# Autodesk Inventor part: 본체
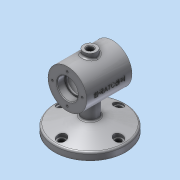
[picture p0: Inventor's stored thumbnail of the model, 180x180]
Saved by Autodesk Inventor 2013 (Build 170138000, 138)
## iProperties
Created: 2018-12
Part Number: 본체
Material: 알루미늄 6061
Document SubType Name: Modeling
Designer: Administrator
Density: 2.71 g/cm^3
Mass: 687.618 g
Surface Area: 555.466 cm^2
Volume: 253.733 cm^3
Author: Administrator
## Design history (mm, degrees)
sketch "스케치1"
  geometry: C1 r 30 at (0, 0); 1 further point
  constraints: 1 centre point, 1 coincident
  dimensions: "d0" = 60 diameter of C1
extrude "돌출1" new body sketch "스케치1" distance "d1" = 35; taper "d2" = 0 deg
sketch "스케치2"
  geometry: C1 r 30 at (0, 0) reference; C2 r 16 at (0, 0)
  constraints: 1 centre point, 1 coincident
  dimensions: "d4" = 32 diameter of C2
extrude "돌출2" cut sketch "스케치2" distance "d5" = 12; taper "d6" = 0 deg
sketch "스케치3"
  geometry: C1 r 16 at (0, 0) reference; C2 r 14 at (0, 0)
  constraints: 1 centre point, 1 coincident
  dimensions: "d7" = 28 diameter of C2
extrude "돌출3" cut sketch "스케치3" distance "d8" = 3; taper "d9" = 0 deg
sketch "스케치4"
  geometry: C1 r 14 at (0, 0) reference; C2 r 25 at (0, 0)
  constraints: 1 centre point, 1 coincident
  dimensions: "d10" = 50 diameter of C2
extrude "돌출4" cut sketch "스케치4" stored distance "d11" = 3; taper "d12" = 0 deg
fillet "모깎기1" dims "d13" = 3
chamfer "모따기1" distance "d14" = 1; stored, may be unused: second distance "d15" = 2, angle "d16" = 45 deg
fillet "모깎기2" dims "d17" = 0.3
sketch "스케치5" dims "d18" = 46
  geometry: C1 r 30 at (0, 0) reference; C2 r 17 at (0, 0) reference; 2 further points
  constraints: 2 vertical alignment, 1 coincident, 2 other
hole "구멍1" sketch "스케치5" at (0, 23) diameter "d19" = 3.242; stored, may be unused: countersink angle "d23" = 90 deg, drill point angle "d25" = 118 deg; dims "d20" = 8, "d21" = 4, "d22" = 2, "d24" = 10
node "작업 평면1"
sketch "스케치6"
  geometry: C1 r 55 at (0, 0); 1 further point
  constraints: 1 centre point, 1 coincident
  dimensions: "d30" = 110 diameter of C1
extrude "돌출5" join sketch "스케치6" distance "d31" = 11; taper "d32" = 0 deg
sketch "스케치9"
  geometry: C1 r 55 at (0, 0) reference; C2 r 12 at (0, 0)
  constraints: 1 centre point, 1 coincident
  dimensions: "d36" = 24 diameter of C2
extrude "돌출7" join sketch "스케치9" stored distance "d37" = 11; taper "d38" = 0 deg
sketch "스케치10"
  geometry: C1 r 55 at (0, 0) reference; C2 r 55 at (0, 0)
  constraints: 1 centre point, 1 coincident
  dimensions: "d39" = 110 diameter of C2
extrude "돌출8" join sketch "스케치10" distance "d40" = 11; taper "d41" = -75 deg
fillet "모깎기3" dims "d42" = 3
node "작업 평면2"
sketch "스케치11"
  geometry: C1 r 10 at (0, 0); 1 further point
  constraints: 1 centre point, 1 coincident
  dimensions: "d44" = 20 diameter of C1
extrude "돌출9" join sketch "스케치11" stored distance "d45" = 11; taper "d46" = 0 deg
sketch "스케치12"
  geometry: C1 r 10 at (0, 0) reference; C2 r 5 at (0, 0)
  constraints: 1 centre point, 1 coincident
  dimensions: "d47" = 10 diameter of C2
extrude "돌출10" cut sketch "스케치12" stored distance "d48" = 11; taper "d49" = 0 deg
chamfer "모따기2" distance "d50" = 1; stored, may be unused: second distance "d51" = 2, angle "d52" = 45 deg
node "작업 평면3"
sketch "스케치13" dims "d54" = 88
  geometry: C1 r 7 at (0, 44); 2 further points
  constraints: 2 vertical alignment, 1 centre point, 1 coincident, 2 other
  dimensions: "d55" = 14 diameter of C1
extrude "돌출11" cut sketch "스케치13" distance "d56" = 11; taper "d57" = 0 deg
sketch "스케치14"
  geometry: C1 r 7 at (0, 0) reference; C2 r 4.5 at (0, 0); 1 further point
  constraints: 1 centre point, 1 coincident
  dimensions: "d58" = 9 diameter of C2
extrude "돌출12" cut sketch "스케치14" stored distance "d59" = 11; taper "d60" = 0 deg
fillet "모깎기4" dims "d64" = 3
fillet "모깎기5" dims "d65" = 3
fillet "모깎기6" dims "d66" = 3
node "작업 평면4"
sketch "스케치15"
  geometry: L1 (30, 35)-(-30, 35) reference; 2 further points
  constraints: 1 other
  dimensions: "d68" = 35 distance from line of point (0, 0) L1; "d69" = 30 horizontal distance of point (0, 0) L1.start
feature "엠보싱1" sketch "스케치15" dims "d70" = 0.5, "d71" = 0
node "솔리드1" dims "d55" = 14
pattern_circular "원형 패턴1" dims angle "d27" = 360 deg
mirror "대칭1"
pattern_circular "원형 패턴2" dims angle "d62" = 360 deg
other parameters: "d29" = -75, "d43" = -112, "d67" = 147
